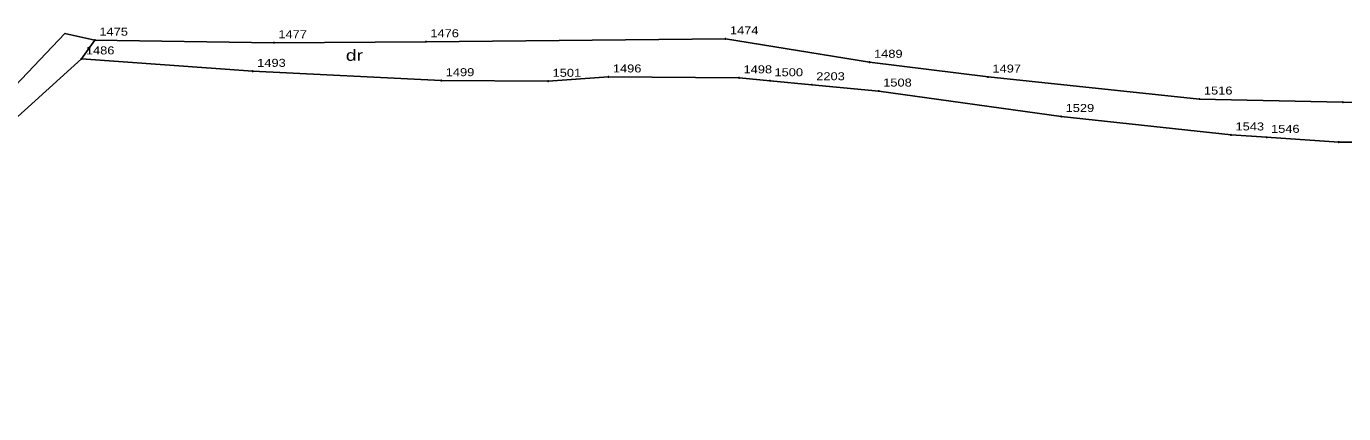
# Model space of a CAD drawing. Extents: x 4640203 to 4641683, y 5358965 to 5360242.
# Drawn here: x 4640428.8 to 4640576.9, y 5360020.3 to 5360063.9 of the extents above; entities that cross this region are included whole.
import ezdxf

# ---------------------------------------------------------------- set-up
doc = ezdxf.new("R2010")
doc.units = 0
doc.header["$LTSCALE"] = 0.36
for name, color, linetype, lineweight in [('25', 7, 'Continuous', 25), ('27', 7, 'Continuous', 25), ('8', 7, 'Continuous', 25)]:
    doc.layers.add(name, color=color, linetype=linetype, lineweight=lineweight)
doc.layers.add('26', color=7, linetype='Continuous')

msp = doc.modelspace()

# ---------------------------------------------------------------- linework, layer by layer
at = {"layer": '25'}
for points in [[(4640616.65, 5360054.35), (4640576.84, 5360055.38), (4640560.72, 5360055.73), (4640536.93, 5360058.21), (4640523.61, 5360059.87), (4640507.4, 5360062.51), (4640473.7, 5360062.18), (4640456.6, 5360062.07), (4640436.47, 5360062.36), (4640434.95, 5360060.25)], [(4640434.95, 5360060.25), (4640454.22, 5360058.85), (4640475.43, 5360057.8), (4640487.45, 5360057.73), (4640494.23, 5360058.22), (4640508.93, 5360058.12), (4640512.41, 5360057.79), (4640517.11, 5360057.34), (4640524.64, 5360056.63), (4640545.16, 5360053.77), (4640564.27, 5360051.69), (4640568.27, 5360051.42), (4640576.38, 5360050.88), (4640589.48, 5360050.86)]]:
    msp.add_lwpolyline(points, dxfattribs=at)
at = {"layer": '27'}
for points in [[(4640707.01, 5360029.39), (4640689.33, 5360027.64), (4640672.34, 5360026.52), (4640663.03, 5360027.26), (4640637.55, 5360039.39), (4640625.49, 5360048.81), (4640616.65, 5360054.35), (4640576.84, 5360055.38), (4640560.72, 5360055.73), (4640536.93, 5360058.21), (4640523.61, 5360059.87), (4640507.4, 5360062.51), (4640473.7, 5360062.18), (4640456.6, 5360062.07), (4640436.47, 5360062.36), (4640433.09, 5360063.11), (4640421.87, 5360051.33)], [(4640420.9, 5360047.53), (4640434.95, 5360060.25), (4640454.22, 5360058.85), (4640475.43, 5360057.8), (4640487.45, 5360057.73), (4640494.23, 5360058.22), (4640508.93, 5360058.12), (4640512.41, 5360057.79), (4640517.11, 5360057.34), (4640524.64, 5360056.63), (4640545.16, 5360053.77)], [(4640545.16, 5360053.77), (4640564.27, 5360051.69), (4640568.27, 5360051.42), (4640576.38, 5360050.88), (4640589.48, 5360050.86), (4640599.77, 5360051.53), (4640611.57, 5360052.21), (4640616.18, 5360050.05), (4640622.1, 5360046.69), (4640631.55, 5360039.15), (4640633.57, 5360037.36), (4640635.67, 5360036.48), (4640638.28, 5360035.17), (4640646.91, 5360030.85), (4640654.24, 5360026.5), (4640662.27, 5360022.36), (4640670.28, 5360020.31)]]:
    msp.add_lwpolyline(points, dxfattribs=at)
at = {"layer": '8'}
for centre in [(4640436.47, 5360062.36), (4640456.6, 5360062.07), (4640473.7, 5360062.18), (4640507.4, 5360062.51), (4640434.95, 5360060.25), (4640454.22, 5360058.85), (4640523.61, 5360059.87), (4640475.43, 5360057.8), (4640487.45, 5360057.73), (4640494.23, 5360058.22), (4640508.93, 5360058.12), (4640512.41, 5360057.79), (4640517.11, 5360057.34), (4640536.93, 5360058.21), (4640524.64, 5360056.63), (4640560.72, 5360055.73), (4640576.84, 5360055.38), (4640545.16, 5360053.77), (4640564.27, 5360051.69), (4640568.27, 5360051.42), (4640576.38, 5360050.88)]:
    msp.add_circle(centre, 0.045, dxfattribs=at)

# ---------------------------------------------------------------- texts
at = {"layer": '26', "width": 1.3}
msp.add_text('dr', height=1.25, dxfattribs=at).set_placement((4640464.69, 5360060.03))
at = {"layer": '8', "width": 1.2}
for s, p in [('1475', (4640436.97, 5360062.86)), ('1477', (4640457.1, 5360062.57)), ('1476', (4640474.2, 5360062.68)), ('1474', (4640507.9, 5360063.01)), ('1486', (4640435.45, 5360060.75)), ('1493', (4640454.72, 5360059.35)), ('1489', (4640524.11, 5360060.37)), ('1499', (4640475.93, 5360058.3)), ('1501', (4640487.95, 5360058.23)), ('1496', (4640494.73, 5360058.72)), ('1498', (4640509.43, 5360058.62)), ('1500', (4640512.91, 5360058.29)), ('2203', (4640517.61, 5360057.84)), ('1497', (4640537.43, 5360058.71)), ('1508', (4640525.14, 5360057.13)), ('1516', (4640561.22, 5360056.23)), ('1529', (4640545.66, 5360054.27)), ('1543', (4640564.77, 5360052.19)), ('1546', (4640568.77, 5360051.92))]:
    msp.add_text(s, height=0.9, dxfattribs=at).set_placement(p)

doc.saveas('drawing.dxf')
